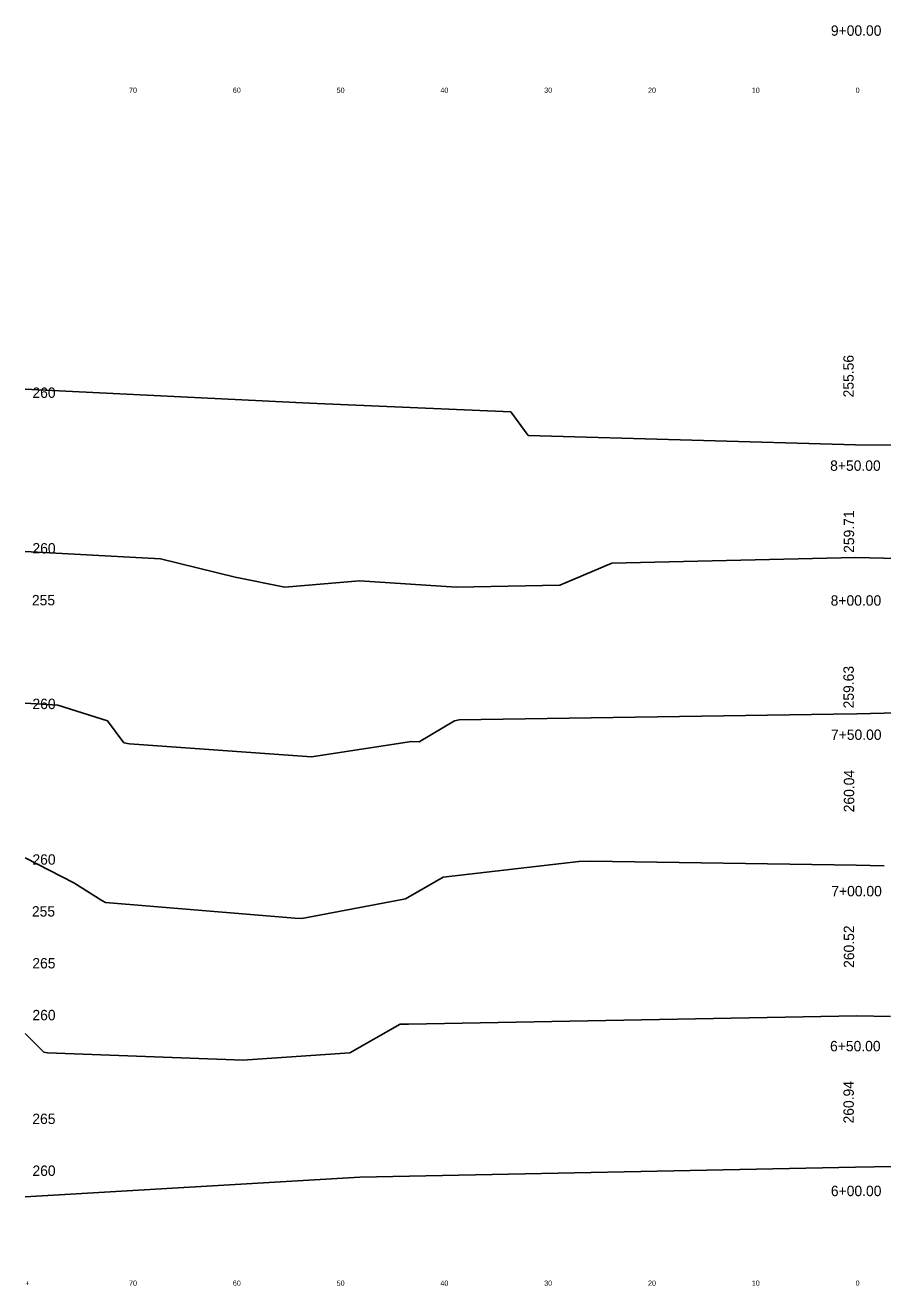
# Model space of a CAD drawing. Extents: x 175484 to 175644, y 176972 to 177478.
# Drawn here: x 175484.1 to 175566.8, y 176972.3 to 177093.8 of the extents above; entities that cross this region are included whole.
import ezdxf

# ---------------------------------------------------------------- set-up
doc = ezdxf.new("R2010")
doc.units = 0
for name, color, linetype in [('Level 10', 7, 'Continuous'), ('Level 2', 7, 'Continuous'), ('Level 3', 7, 'Continuous'), ('Level 60', 7, 'Continuous')]:
    doc.layers.add(name, color=color, linetype=linetype)

msp = doc.modelspace()

# ---------------------------------------------------------------- linework, layer by layer
at = {"layer": 'Level 60'}
for p, q in [((175484.13, 177058.72), (175511.51, 177057.39)), ((175511.51, 177057.39), (175530.9, 177056.56)), ((175530.9, 177056.56), (175532.6, 177054.25)), ((175532.6, 177054.25), (175564.13, 177053.36)), ((175564.13, 177053.36), (175593.72, 177053.22)), ((175484.13, 177043.07), (175497.17, 177042.38)), ((175497.17, 177042.38), (175504.36, 177040.61)), ((175536.87, 177040.36), (175540.63, 177041.95)), ((175540.63, 177041.95), (175564.13, 177042.51)), ((175564.13, 177042.51), (175579.26, 177042.12)), ((175504.36, 177040.61), (175509.15, 177039.63)), ((175509.15, 177039.63), (175516.34, 177040.25)), ((175516.34, 177040.25), (175525.69, 177039.65)), ((175525.69, 177039.65), (175535.63, 177039.82)), ((175535.63, 177039.82), (175536.87, 177040.36)), ((175484.13, 177028.45), (175485.73, 177028.36)), ((175485.73, 177028.36), (175487.27, 177028.28)), ((175487.27, 177028.28), (175492.05, 177026.75)), ((175525.94, 177026.84), (175561.99, 177027.4)), ((175561.99, 177027.4), (175564.26, 177027.43)), ((175564.26, 177027.43), (175585.56, 177027.9)), ((175492.05, 177026.75), (175493.62, 177024.63)), ((175522.07, 177024.73), (175525.5, 177026.77)), ((175525.5, 177026.77), (175525.94, 177026.84)), ((175511.71, 177023.3), (175521.36, 177024.78)), ((175521.36, 177024.78), (175522.07, 177024.73)), ((175493.62, 177024.63), (175494.18, 177024.55)), ((175494.18, 177024.55), (175511.71, 177023.3)), ((175484.13, 177013.56), (175488.82, 177011.14)), ((175524.4, 177011.68), (175537.47, 177013.2)), ((175537.47, 177013.2), (175538.58, 177013.22)), ((175538.58, 177013.22), (175564.18, 177012.84)), ((175564.18, 177012.84), (175566.89, 177012.77)), ((175520.77, 177009.59), (175524.4, 177011.68)), ((175488.82, 177011.14), (175491.5, 177009.43)), ((175491.5, 177009.43), (175491.85, 177009.23)), ((175491.85, 177009.23), (175510.09, 177007.75)), ((175510.78, 177007.7), (175520.43, 177009.53)), ((175520.43, 177009.53), (175520.77, 177009.59)), ((175510.09, 177007.75), (175510.78, 177007.7)), ((175521.04, 176997.51), (175564.25, 176998.32)), ((175564.25, 176998.32), (175567.48, 176998.27)), ((175515.4, 176994.75), (175520.24, 176997.5)), ((175520.24, 176997.5), (175521.04, 176997.51)), ((175484.13, 176996.62), (175485.92, 176994.81)), ((175485.92, 176994.81), (175486.28, 176994.76)), ((175486.28, 176994.76), (175505.16, 176994.05)), ((175505.54, 176994.07), (175515.4, 176994.75)), ((175505.16, 176994.05), (175505.54, 176994.07)), ((175516.36, 176982.76), (175564.13, 176983.74)), ((175564.13, 176983.74), (175582.58, 176984)), ((175484.13, 176980.87), (175516.36, 176982.76))]:
    msp.add_line(p, q, dxfattribs=at)

# ---------------------------------------------------------------- texts
at = {"layer": 'Level 10'}
for s, p in [('9+00.00', (175561.75, 177092.8)), ('8+50.00', (175561.68, 177050.86)), ('8+00.00', (175561.73, 177037.86)), ('7+50.00', (175561.76, 177024.92)), ('7+00.00', (175561.79, 177009.84)), ('6+50.00', (175561.67, 176994.9)), ('6+00.00', (175561.75, 176980.94))]:
    msp.add_text(s, height=1, dxfattribs=at).set_placement(p)
for s, p in [('255.56', (175563.95, 177057.94)), ('259.71', (175563.99, 177042.95)), ('259.63', (175563.96, 177027.96)), ('260.04', (175564, 177017.94)), ('260.52', (175563.99, 177002.94)), ('260.94', (175563.96, 176987.94))]:
    msp.add_text(s, height=1, rotation=90, dxfattribs=at).set_placement(p)
at = {"layer": 'Level 2'}
for s, p in [('70', (175494.13, 177087.3)), ('60', (175504.13, 177087.3)), ('50', (175514.13, 177087.3)), ('40', (175524.13, 177087.3)), ('30', (175534.13, 177087.3)), ('20', (175544.13, 177087.3)), ('10', (175554.13, 177087.3)), ('0', (175564.13, 177087.3)), ('+', (175484.13, 176972.3)), ('70', (175494.13, 176972.3)), ('60', (175504.13, 176972.3)), ('50', (175514.13, 176972.3)), ('40', (175524.13, 176972.3)), ('30', (175534.13, 176972.3)), ('20', (175544.13, 176972.3)), ('10', (175554.13, 176972.3)), ('0', (175564.13, 176972.3))]:
    msp.add_text(s, height=0.5, dxfattribs=at).set_placement(p)
at = {"layer": 'Level 3'}
for s, p in [(' 260', (175484.45, 177057.89)), (' 260', (175484.45, 177042.89)), (' 255', (175484.4, 177037.89)), (' 260', (175484.45, 177027.89)), (' 260', (175484.45, 177012.89)), (' 255', (175484.4, 177007.89)), (' 265', (175484.44, 177002.89)), (' 260', (175484.45, 176997.89)), (' 265', (175484.44, 176987.89)), (' 260', (175484.45, 176982.89))]:
    msp.add_text(s, height=1, dxfattribs=at).set_placement(p)

doc.saveas('drawing.dxf')
